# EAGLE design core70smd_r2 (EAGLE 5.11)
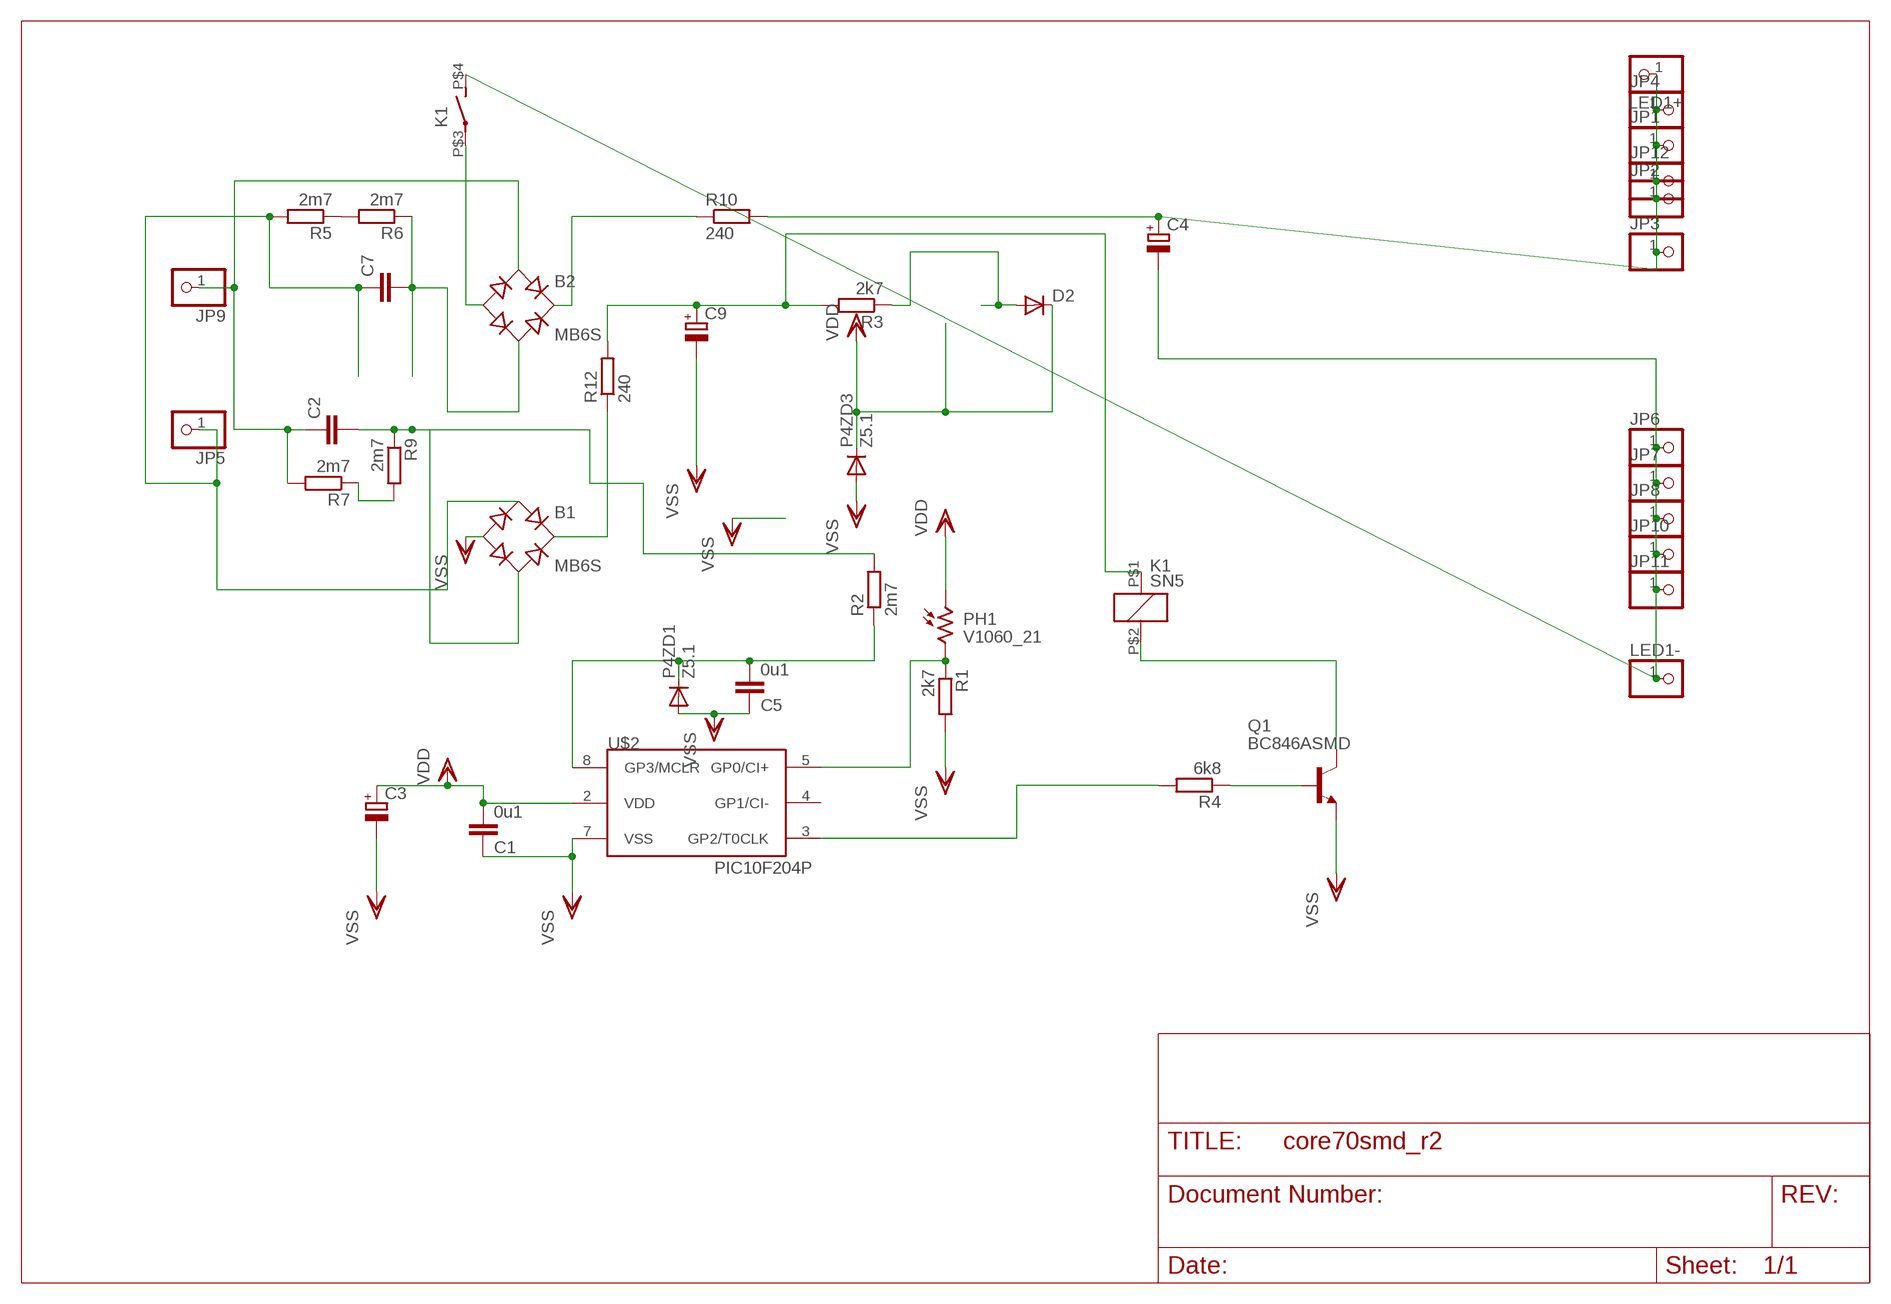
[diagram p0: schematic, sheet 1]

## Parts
B1  MB6S  [SOIC-4]
B2  MB6S  [SOIC-4]
C1  0u1  C-EUC1206  [C1206]
C2  C-EU075-063X106  [C075-063X106]
C3  CPOL-EUD  [PANASONIC_D]
C4  CPOL-EUE7.5-18  [E7,5-18]
C5  0u1  C-EUC1206  [C1206]
C7  C-EU225-062X268  [C225-062X268]
C9  CPOL-EUD  [PANASONIC_D]
D2  DIODE-MINIMELF  [MINIMELF]
JP1  PINHD-1X11MM6  [1X1MM8]
JP2  PINHD-1X11MM6  [1X1MM8]
JP3  PINHD-1X11MM6  [1X1MM8]
JP4  PINHD-1X11MM6  [1X1MM8]
JP5  PINHD-1X1  [1X01]
JP6  PINHD-1X11MM6  [1X1MM8]
JP7  PINHD-1X11MM6  [1X1MM8]
JP8  PINHD-1X11MM6  [1X1MM8]
JP9  PINHD-1X1  [1X01]
JP10  PINHD-1X11MM6  [1X1MM8]
JP11  PINHD-1X11MM6  [1X1MM8]
JP12  PINHD-1X11MM6  [1X1MM8]
K1  SN5  [HU]
LED1+  PINHD-1X1  [1X01]
LED1-  PINHD-1X1  [1X01]
P4ZD1  Z5.1  DIODE-MINIMELF  [MINIMELF]
P4ZD3  Z5.1  DIODE-MINIMELF  [MINIMELF]
PH1  V1060_21  [TO-5_V10]
Q1  BC846ASMD  [SOT23]
R1  2k7  R-EU_R1206  [R1206]
R2  2m7  R-EU_R1206  [R1206]
R3  2k7  R-EU_R1206  [R1206]
R4  6k8  R-EU_R1206  [R1206]
R5  2m7  R-EU_R1210  [R1210]
R6  2m7  R-EU_R1210  [R1210]
R7  2m7  R-EU_R1210  [R1210]
R9  2m7  R-EU_R1210  [R1210]
R10  240  R-EU_0617/22  [0617/22]
R12  240  R-EU_0617/22  [0617/22]
U$2  PIC10F204P  [DIL8]

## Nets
AC1: B1.~1(AC1) C7.1 JP5.1 R5.2
AC2: B2.~1(AC1) C2.1 JP9.1 R7.2
CBIG: B2.~2(AC2) C7.2 R6.1
CSMALL: B1.~2(AC2) C2.2 R2.2 R9.1
D+: C4.+ JP1.1 JP2.1 JP3.1 JP4.1 JP12.1 LED1+.1 R10.2
D-: C4.- JP6.1 JP7.1 JP8.1 JP10.1 JP11.1 K1.P$4(2:S) LED1-.1
DR+: C9.+ K1.P$1 R3.2 R12.2
N$1: C5.2 P4ZD1.C R2.1 U$2.8(GP3/MCLR)
N$2: R5.1 R6.2
N$3: R7.1 R9.2
N$5: D2.A R3.1
N$6: B2.+ R10.1
N$9: B2.- K1.P$3(2:P)
N$12: Q1.1(B) R4.1
N$13: K1.P$2 Q1.3(C)
N$15: R4.2 U$2.3(GP2/T0CLK)
N$17: PH1.2 R1.1 U$2.5(GP0/CI+)
RECDR+: B1.+ R12.1
VDD: C1.2 C3.+ D2.C P4ZD3.C PH1.1 U$2.2(VDD)
VSS: B1.- C1.1 C3.- C5.1 C9.- P4ZD1.A P4ZD3.A Q1.2(E) R1.2 U$2.7(VSS)
Unconnected: U$2.4(GP1/CI-)

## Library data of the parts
B1 B2 = rectifier:MB*S: Bridge Rectifier Source: http://www.fairchildsemi.com/ds/MB/MB6S.pdf
C1 C5 = rcl:C-EU: CAPACITOR, European symbol
C2 C7 = rcl-2:C-EU: CAPACITOR, European symbol
C3 C4 C9 = rcl-2:CPOL-EU: POLARIZED CAPACITOR, European symbol
D2 P4ZD1 P4ZD3 = diode:DIODE-: DIODE
JP1-JP4 JP6-JP8 JP10-JP12 = pinhead:PINHD-1X1: PIN HEADER
JP5 JP9 LED1+ LED1- = pinhead(2):PINHD-1X1: PIN HEADER
K1 = relay:SN*: Slim PCB Relay 1 pole 6 A SCHRACK Source: http://www.schrack.com/.. 5815.pdf
PH1 = photo-elements:?1060*: Sensor Street Light control
Q1 = transistor-npn:BC846*: NPN Transistor
R1-R7 R9 R10 R12 = rcl-2:R-EU_: RESISTOR, European symbol
U$2 = microchip-3:PIC10F2*: uPC nW 0,25/0,5k Program Flash memory Comparator

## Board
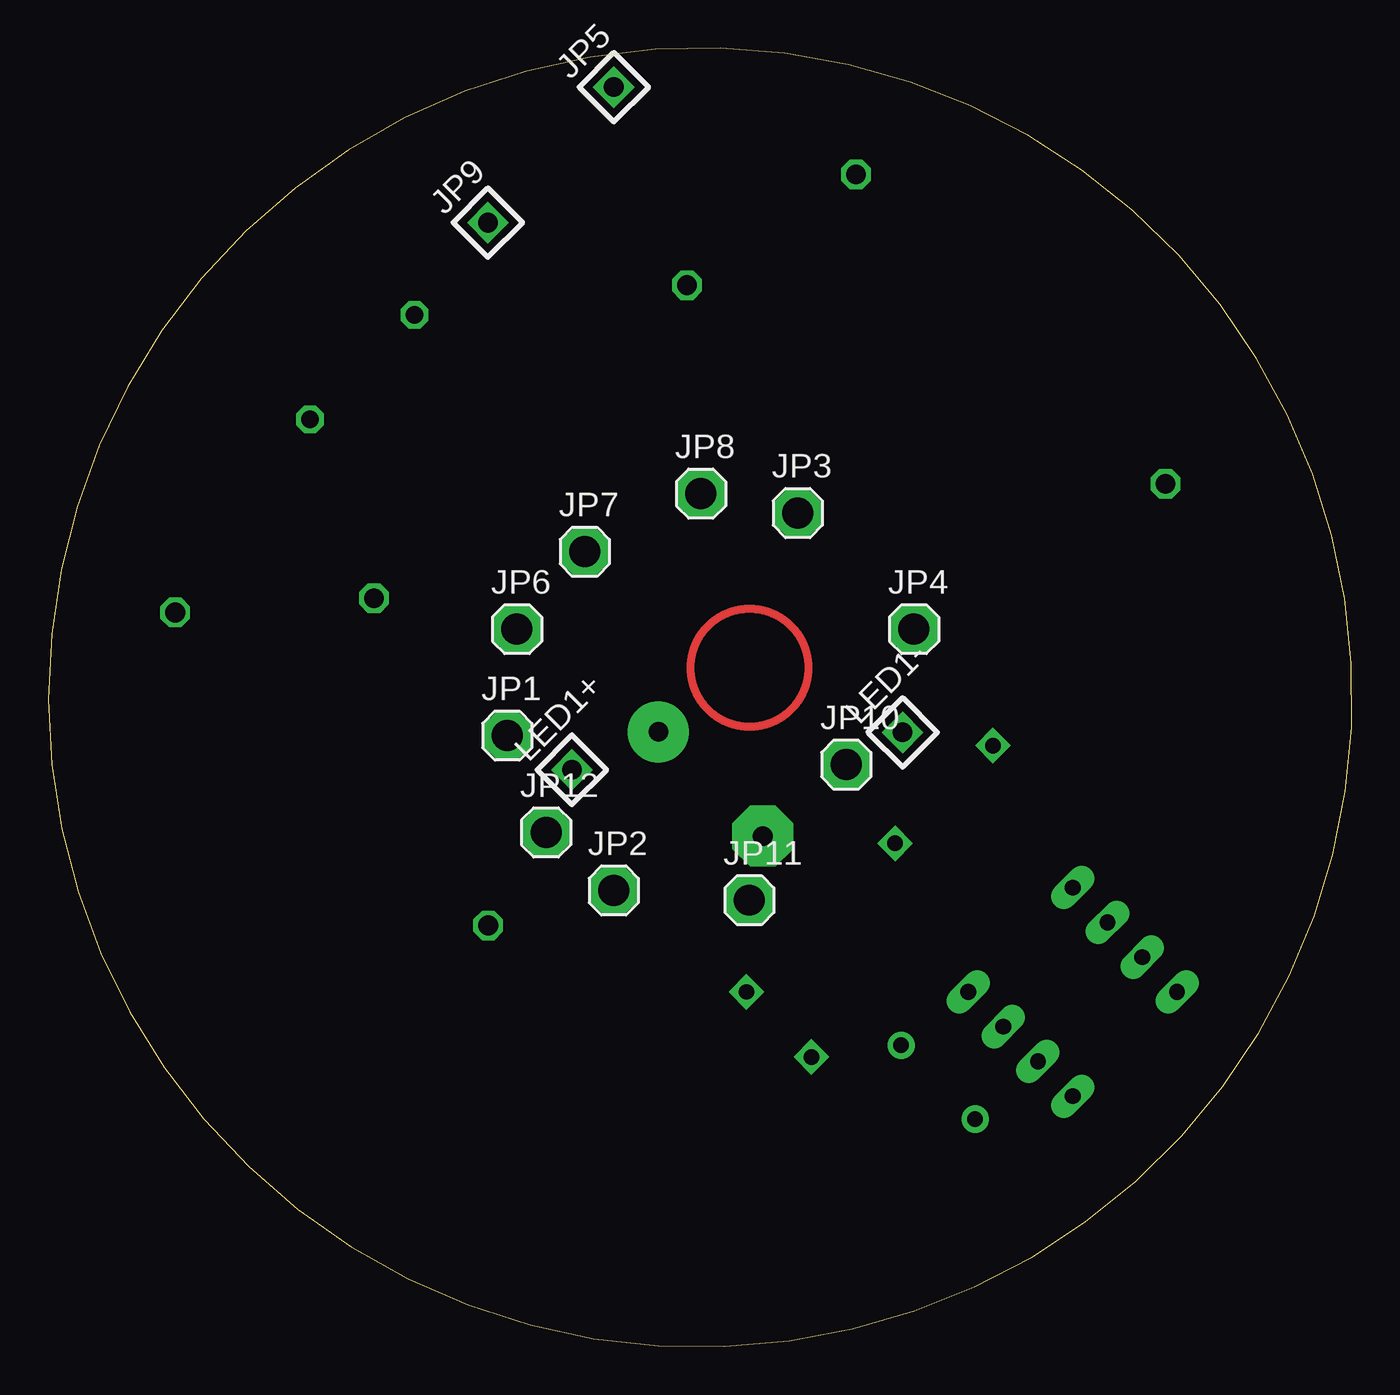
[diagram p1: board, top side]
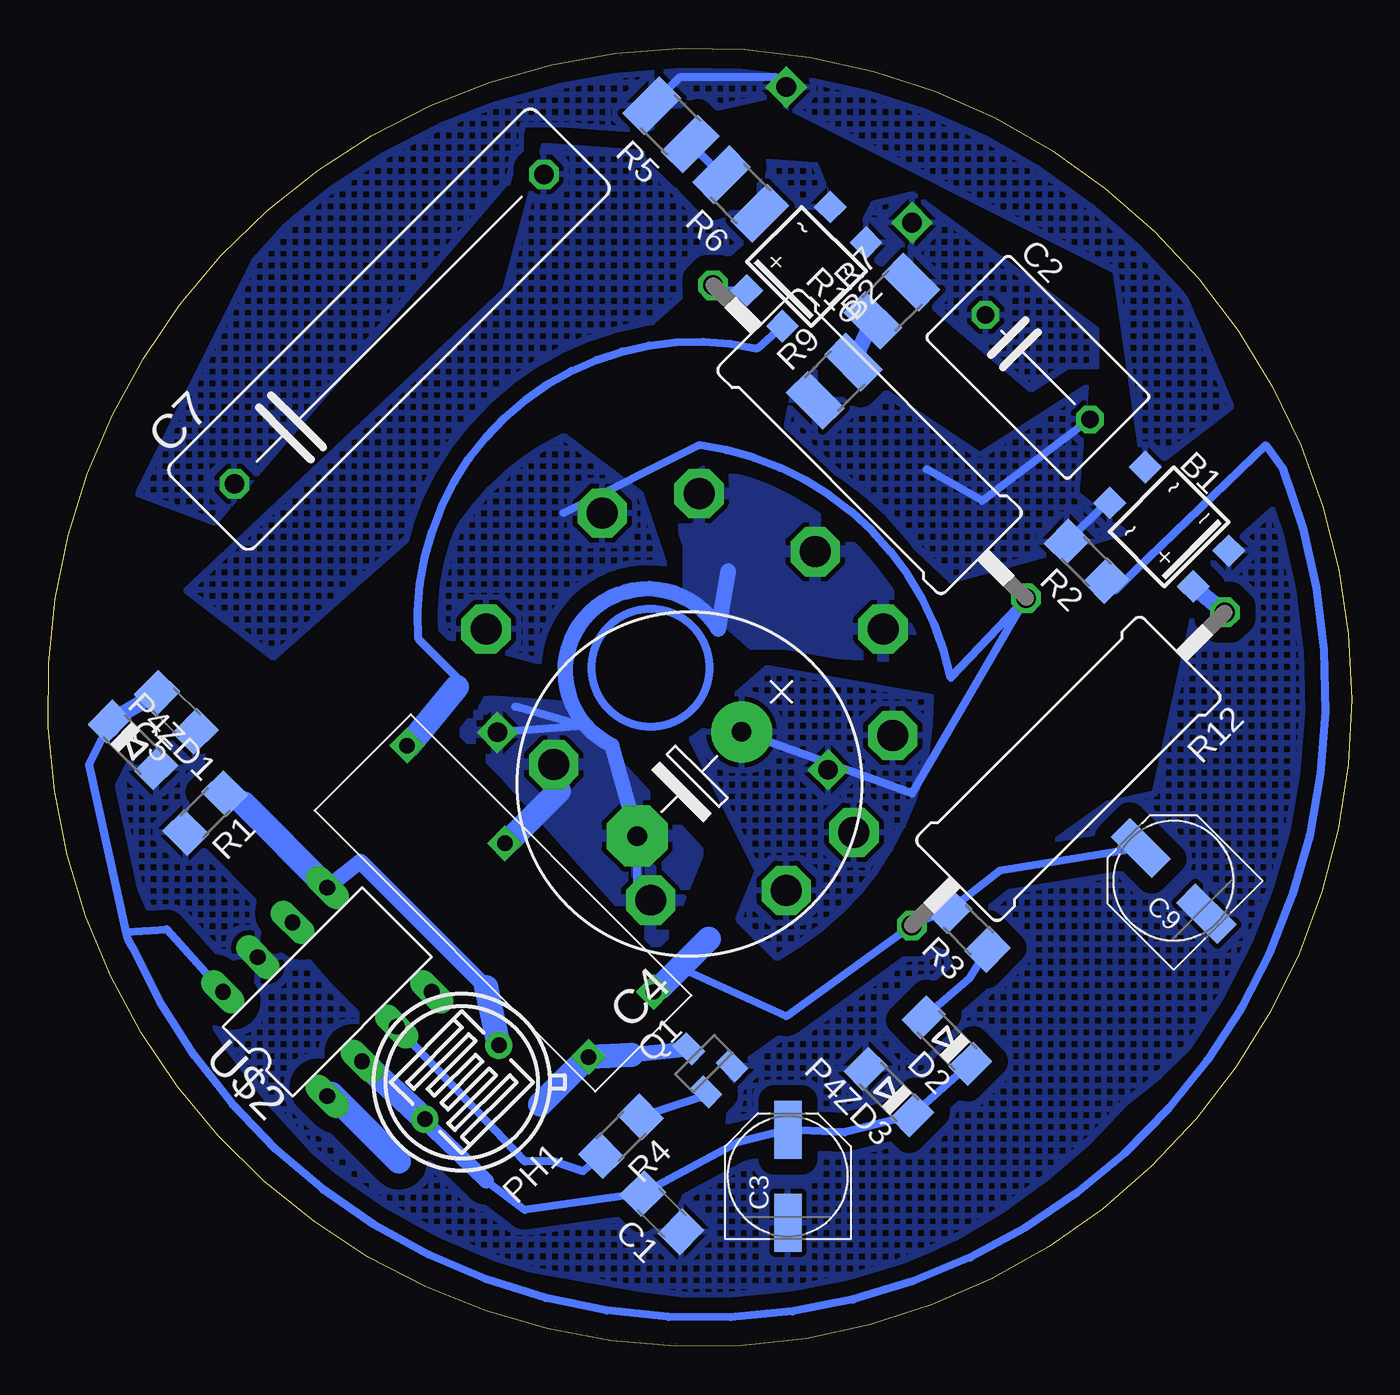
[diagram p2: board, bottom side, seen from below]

Size 67.29 x 67.05 mm. Coordinates in mm from the lower left corner, seen from the top.
Outline: 38.24,0.3 arc171 34.69,67.05 arc190 38.24,0.3
Copper layers (1*16): Top 0.035mm / dielectric 1.5mm / Bottom 0.035mm
Design rules "default": minimum track width 10mil, minimum drill 24mil, track to track 8mil, track to pad 8mil, pad to pad 8mil, via to via 8mil, smd to smd 8mil, copper to edge 40mil, drill to drill 8mil, minimum pad ring 10mil, minimum via ring 8mil, stop-mask expansion 4mil, vias tented up to drill 0mil, thermal gap 10mil

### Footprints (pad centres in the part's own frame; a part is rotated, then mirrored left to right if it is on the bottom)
SOIC-4 = smd 1.2 x 1.2: + 1.3,3.05; - -1.3,3.05; ~1 -1.3,-3.05; ~2 1.3,-3.05
C1206 = smd 1.6 x 1.8: 1 -1.4,0; 2 1.4,0
C075-063X106 = drill 0.914 octagon: 1 -3.81,0; 2 3.81,0
PANASONIC_D = smd 3 x 1.4: + 2.4,0; - -2.4,0
E7,5-18 = drill 1.016 pad 3.15 round: + -3.81,0 | drill 1.016 pad 3.15 octagon: - 3.81,0
C225-062X268 = drill 1.016 octagon: 1 -11.303,0; 2 11.303,0
MINIMELF = smd 1.4 x 1.8: A 1.7,0; C -1.7,0
1X1MM8 = drill 1.6 pad 2.54 octagon: 1 0,0
1X01 = drill 1.016 square: 1 0,0
HU = drill 0.8 square: P$1 2.25,-9; P$2 -2.5,-9; P$3 2.25,9; P$4 2.25,1.85
TO-5_V10 = drill 0.8 pad 1.4 round: 1 -2.7,0; 2 2.7,0
SOT23 = smd 1 x 1.4: 1 -0.95,-1.1; 2 0.95,-1.1; 3 0,1.1
R1206 = smd 1.6 x 1.803: 1 -1.422,0; 2 1.422,0
R1210 = smd 1.6 x 2.7: 1 -1.4,0; 2 1.4,0
0617/22 = drill 1.016 octagon: 1 -11.43,0; 2 11.43,0
DIL8 = drill 0.813 long: 1 -3.81,-3.81; 2 -1.27,-3.81; 3 1.27,-3.81; 4 3.81,-3.81; 5 3.81,3.81; 6 1.27,3.81; 7 -1.27,3.81; 8 -3.81,3.81

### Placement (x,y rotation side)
B1  9.42,42.34 225 bottom
B2  28.15,55.79 135 bottom
C1  35.61,6.91 135 bottom
C2  16.2,50.59 315 bottom
C3  29.1,8.8 90 bottom
C4  34.19,29.05 225 bottom
C5  60.69,32.76 135 bottom
C7  49.69,52.55 45 bottom
C9  9.19,24.05 135 bottom
D2  20.89,15.8 135 bottom
JP1  23.69,31.55 0 top
JP2  29.19,23.55 0 top
JP3  38.69,43.05 0 top
JP4  44.69,37.05 0 top
JP5  29.19,65.05 45 top
JP6  24.19,37.05 0 top
JP7  27.69,41.05 0 top
JP8  33.69,44.05 0 top
JP9  22.69,58.05 45 top
JP10  41.19,30.05 0 top
JP11  36.19,23.05 0 top
JP12  25.69,26.55 0 top
K1  44,23.09 45 bottom
LED1+  27.03,29.79 45 top
LED1-  44.1,31.72 45 top
P4ZD1  62.93,31.08 315 bottom
P4ZD3  23.89,13.14 135 bottom
PH1  45.95,13.65 45 bottom
Q1  33.44,14.6 45 bottom
R1  59.19,27.55 225 bottom
R2  13.69,40.55 135 bottom
R3  19.8,21.51 135 bottom
R4  37.72,10.86 225 bottom
R5  35.14,63.11 135 bottom
R6  31.55,59.54 135 bottom
R7  23.74,54 45 bottom
R9  26.71,49.86 45 bottom
R10  24.89,46.74 315 bottom
R12  14.63,29.83 225 bottom
U$2  52.89,18.32 45 bottom

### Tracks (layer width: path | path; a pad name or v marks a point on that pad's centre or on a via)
AC1
  Bottom 0.406: R5.2 36.13,64.12 34.69,65.55 29.69,65.55 JP5.1
  pour Bottom (isolate 0.813, rank 4, hatched): 27.19,67.05 40.19,66.05 arc-39 56.69,56.05 62.69,44.05 58.69,42.55 43.69,60.05 34.69,63.55 30.19,64.55 12.19,55.55 10.69,45.05 6.19,48.55 9.19,55.55 arc-37
AC2
  pour Bottom (isolate 0.813, rank 4, hatched): 24.69,59.05 22.69,59.55 13.19,52.55 13.19,46.55 23.19,55.05 25.69,57.05
CBIG
  pour Bottom (isolate 0.813, rank 3, hatched): 41.69,62.05 27.69,61.05 26.69,58.55 29.19,59.05 55.69,35.55 60.19,39.05 43.69,54.55
CSMALL
  Bottom 0.406: C2.2 19.08,43.68 21.94,45.32 | B1.~2 12.68,43.58 R2.2
  pour Bottom (isolate 0.813, rank 3, hatched): 26.69,51.05 28.69,50.05 29.19,47.55 20.69,39.55 11.69,42.05 14.19,44.05 13.69,49.55 19.19,46.05
D+
  Bottom 0.406: 40.69,43.05 33.69,46.55 arc71 20.69,34.55 R10.2 22.69,28.55 C4.+
  pour Bottom (isolate 0.813, hatched): 40.69,47.05 arc-54 48.19,37.05 40.69,35.05 35.19,39.55 36.69,44.05
  pour Bottom (isolate 0.813, hatched): 29.69,20.05 arc-62 21.69,33.55 30.19,35.05 34.19,31.55 30.69,24.55 31.69,22.05
D-
  Bottom 0.406: 43.19,33.05 39.69,32.05 LED1-.1 | C4.- 36.89,23.75 JP11.1 | JP10.1 41.19,28.95 40.94,28.7 | 43.44,26.2 43.54,26.2 | K1.P$4 43.66,25.99 43.14,26.5
  Bottom 0.813: C4.- 38.19,31.05 arc214 32.69,37.05 32.19,40.05
  Bottom 1.27: 40.94,28.7 43.14,26.5 43.44,26.2
  pour Bottom (isolate 0.813, rank 2): 43.69,29.55 35.69,20.55 33.69,25.55 40.69,33.05 47.69,33.55
  pour Bottom (isolate 0.813, rank 2): 22.69,37.55 arc-67 34.19,46.05 34.69,39.55 30.69,36.05 22.19,35.55
DR+
  Bottom 0.406: C9.+ 18.19,24.55 R3.2 R12.2 29.19,17.05 34.69,19.55 | K1.P$1 35.93,18.32 35.69,18.55
  Bottom 1.27: 33.19,21.05 34.69,19.55 35.69,18.55
N$1
  Bottom 0.406: 64.19,32.05 65.19,30.05 63.28,21.42 | 63.28,21.42 63.19,21.05 62.94,20.6 arc-177 3.54,45.35 4.44,46.55 11.19,40.05 12.19,39.05 R2.1 | U$2.8 61.19,21.55 63.28,21.42
  Bottom 0.813: P4ZD1.C C5.2
  Bottom 1.27: 64.19,32.05 P4ZD1.C
N$2
  Bottom 0.406: R5.1 34.13,62.12 R6.2
N$3
  Bottom 0.813: R7.1 R9.2
N$5
  Bottom 0.406: D2.A 19.69,19.05 R3.1
N$6
  Bottom 0.406: B2.+ 32.7,54.55 R10.1
N$8
  Bottom 1.27: 49.19,9.55 52.69,13.05
N$9
  Bottom 0.406: K1.P$3 46.19,34.55 48.19,36.55 arc107 30.69,51.55 B2.-
N$12
  Bottom 0.406: R4.1 33.63,12.86 Q1.1
N$13
  Bottom 0.813: Q1.3 37.19,15.05
  Bottom 1.27: 37.19,15.05 K1.P$2
N$14
  Bottom 1.27: 48.69,31.05 46.19,34.05
N$15
  Bottom 0.406: U$2.3 42.69,9.55 41.19,9.55 39.69,9.05 R4.2
N$16
  Bottom 1.27: 41.89,12.5 39.39,15
N$17
  Bottom 0.813: 44.69,18.55 51.19,25.05 U$2.5 | 57.19,28.05 R1.1
  Bottom 1.27: PH1.2 44.69,18.55 | U$2.5 57.19,28.05
RECDR+
  Bottom 0.813: R12.1 B1.+
VDD
  Bottom 0.406: 44.69,8.55 42.69,7.05 C1.2 31.69,10.55 C3.+ 26.19,11.05 P4ZD3.C D2.C
  Bottom 0.813: 44.69,8.55 U$2.2
  Bottom 1.27: U$2.2 PH1.1
VSS
  pour Bottom (isolate 0.813, rank 4, hatched): 3.19,44.05 7.69,40.05 10.19,28.55 12.59,28.05 32.04,14.15 32.19,11.55 34.69,9.05 38.54,8.1 48.84,14.7 52.69,18.55 56.19,22.55 59.69,26.05 59.19,32.05 63.19,30.05 64.19,28.05 arc-37 48.09,5.25 arc-8 31.09,2.25 arc-42 11.69,12.55 arc-47 1.69,29.55
(copper drawn outside any net)
  shapes: Bottom circle x1, Top circle x1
